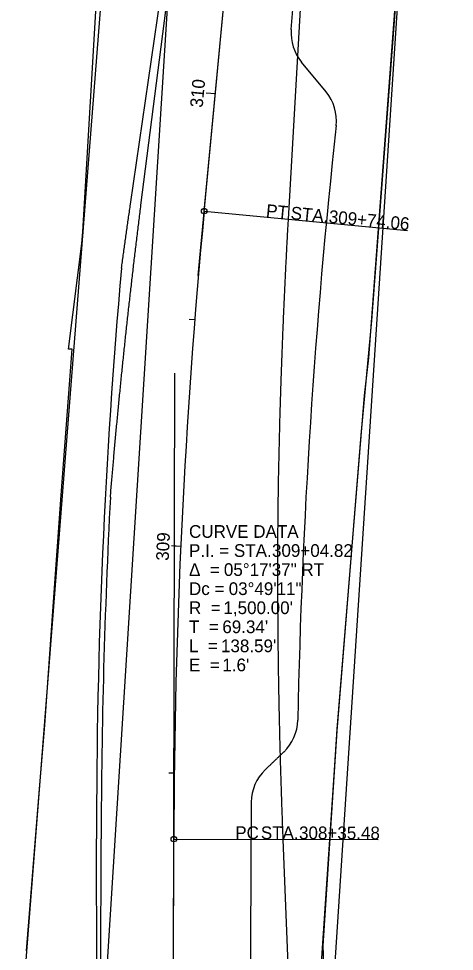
# Model space of a CAD drawing. Extents: x 219353 to 221640, y 361458 to 364236.
# Drawn here: x 220538 to 220633.9, y 362269.2 to 362474.7 of the extents above; entities that cross this region are included whole.
import ezdxf

# ---------------------------------------------------------------- set-up
doc = ezdxf.new("R2010")
doc.units = 0
for name, color, linetype in [('Default', 7, 'Continuous'), ('DR_X_Cells', 7, 'Continuous'), ('DR_X_GenericNode', 7, 'Continuous'), ('DR_X_Storm_Sewer', 7, 'Continuous'), ('DT_X_Contour_Major', 7, 'Continuous'), ('DT_X_Contour_Minor', 7, 'Continuous'), ('SC_ProfileRun2', 7, 'Continuous'), ('SC_ProfileRun3', 7, 'Continuous'), ('UT_X_Sanitary_Cells', 7, 'Continuous')]:
    doc.layers.add(name, color=color, linetype=linetype)

msp = doc.modelspace()

# ---------------------------------------------------------------- linework, layer by layer
at = {"layer": 'Default'}
for p, q in [((220606.11, 362243.12), (220684.52, 363442.47)), ((220589.94, 362047.45), (220608.12, 362317.78))]:
    msp.add_line(p, q, dxfattribs=at)
msp.add_open_spline([(220592.27, 362309.18), (220592.28, 362309.19), (220592.45, 362309.35), (220592.79, 362309.68), (220593.29, 362310.16), (220593.8, 362310.65), (220594.31, 362311.13), (220594.81, 362311.62), (220595.32, 362312.11), (220595.83, 362312.59), (220596.18, 362312.92), (220596.35, 362313.1), (220596.37, 362313.11)], degree=3, dxfattribs=at)
at = {"layer": 'DR_X_Cells'}
for p, q in [((220578.85, 362432.29), (220623.65, 362428.04)), ((220572.17, 362293.91), (220617.17, 362293.82))]:
    msp.add_line(p, q, dxfattribs=at)
for centre in [(220578.85, 362432.29), (220572.17, 362293.91)]:
    msp.add_circle(centre, 0.6, dxfattribs=at)
at = {"layer": 'DR_X_GenericNode'}
for p, q in [((220631.67, 363446.41), (220538.01, 362247.29)), ((220541.47, 362010.88), (220631.67, 363446.41)), ((220562.63, 362433.83), (220580.78, 362558.61)), ((220598.01, 362472.29), (220604.67, 362556.35)), ((220615.74, 362408.19), (220621, 362477.12)), ((220605.68, 362458.59), (220600.27, 362465.13)), ((220613.44, 362382.96), (220615.74, 362408.19)), ((220608.12, 362317.78), (220613.44, 362382.96)), ((220605.04, 362270.37), (220608.12, 362317.78)), ((220555.31, 362213.3), (220555.17, 362293.95)), ((220589.06, 362242.18), (220589.17, 362293.88)), ((220606.11, 362243.12), (220605.04, 362270.37))]:
    msp.add_line(p, q, dxfattribs=at)
for centre, radius, start, end in [((220607.98, 362471.5), 10, 175.4681, 219.5875), ((220597.98, 362452.21), 10, 353.7514, 39.5875), ((222072.17, 362290.8), 1473, 173.75144, 178.85872), ((221945.54, 362296.32), 1390.38, 174.90785, 180.0978), ((220589.46, 362320.34), 10, 313.6715, 358.8587), ((220599.21, 362301.98), 10, 133.9039, 179.5652), ((222072.17, 362290.8), 1483, 179.5652, 179.88107)]:
    msp.add_arc(centre, radius, start, end, dxfattribs=at)
msp.add_open_spline([(220560.65, 362419.73), (220560.69, 362419.96), (220560.75, 362420.43), (220560.85, 362421.14), (220560.94, 362421.85), (220561.04, 362422.55), (220561.14, 362423.26), (220561.23, 362423.96), (220561.33, 362424.67), (220561.43, 362425.37), (220561.53, 362426.08), (220561.63, 362426.78), (220561.72, 362427.48), (220561.82, 362428.19), (220561.92, 362428.89), (220562.02, 362429.6), (220562.12, 362430.3), (220562.22, 362431.01), (220562.32, 362431.71), (220562.43, 362432.42), (220562.53, 362433.12), (220562.6, 362433.59), (220562.63, 362433.83)], degree=3, dxfattribs=at)
at = {"layer": 'DT_X_Contour_Major'}
for p, q in [((220577.51, 362418.1), (220596.38, 362617.24)), ((220578.85, 362432.29), (220596.38, 362617.24)), ((220571.7, 362066.21), (220572.38, 362396.56)), ((220571.7, 362066.21), (220572.17, 362293.91)), ((220571.8, 362118.35), (220572.17, 362293.91)), ((220571.8, 362118.35), (220572.17, 362293.91))]:
    msp.add_line(p, q, dxfattribs=at)
msp.add_arc((222072.17, 362290.8), 1500, 174.58751, 179.88107, dxfattribs=at)
msp.add_arc((222072.17, 362290.8), 1500, 174.58751, 179.88107, dxfattribs=at)
at = {"layer": 'DT_X_Contour_Minor'}
for p, q in [((220564.94, 362433.61), (220580.78, 362558.61)), ((220564.94, 362433.61), (220580.78, 362558.61)), ((220564.94, 362433.61), (220580.78, 362558.61)), ((220564.94, 362433.61), (220580.78, 362558.61)), ((220564.94, 362433.61), (220580.78, 362558.61)), ((220597.41, 362430.53), (220604.67, 362556.35)), ((220597.41, 362430.53), (220604.67, 362556.35)), ((220597.41, 362430.53), (220604.67, 362556.35)), ((220615.12, 362399.96), (220622.66, 362501.46)), ((220615.12, 362399.96), (220622.66, 362501.46)), ((220614.15, 362391.69), (220615.12, 362399.96)), ((220614.15, 362391.69), (220615.12, 362399.96)), ((220555.92, 362173.47), (220556.17, 362293.95)), ((220555.92, 362173.47), (220556.17, 362293.95)), ((220556.01, 362215.03), (220556.17, 362293.95)), ((220556.01, 362215.03), (220556.17, 362293.95)), ((220556.01, 362215.03), (220556.17, 362293.95)), ((220599.02, 362223.38), (220596.25, 362293.86)), ((220598.09, 362247.17), (220596.25, 362293.86)), ((220598.09, 362247.17), (220596.25, 362293.86))]:
    msp.add_line(p, q, dxfattribs=at)
for points in [[(220548.97, 362401.87), (220551.9, 362425.19), (220552.11, 362427.73), (220555.49, 362485.14), (220558.19, 362519.47), (220559.13, 362527.53), (220560.7, 362544.5), (220563.39, 362577.56), (220564.51, 362592.82), (220566.29, 362622.53), (220566.62, 362624.87), (220555.18, 362626.91)], [(220539.71, 362269.28), (220542.65, 362305.9), (220543.74, 362319.05), (220545.68, 362346.19), (220547.38, 362369.7), (220549.8, 362401.88), (220548.97, 362401.87)], [(220604.98, 362269.51), (220608.14, 362318.12), (220614.15, 362391.69)], [(220604.98, 362269.51), (220608.14, 362318.12), (220614.15, 362391.69)]]:
    msp.add_lwpolyline(points, dxfattribs=at)
msp.add_arc((222072.17, 362290.8), 1516, 177.03444, 179.88107, dxfattribs=at)
msp.add_arc((222072.17, 362290.8), 1516, 177.03444, 179.88107, dxfattribs=at)
msp.add_arc((222072.17, 362290.8), 1516, 177.03444, 179.88107, dxfattribs=at)
msp.add_arc((222072.17, 362290.8), 1516, 177.03444, 179.88107, dxfattribs=at)
msp.add_arc((222072.17, 362290.8), 1516, 177.03444, 179.88107, dxfattribs=at)
for points in [[(220558.2, 362369.23), (220558.29, 362370.31), (220558.47, 362372.46), (220558.75, 362375.68), (220559.03, 362378.91), (220559.32, 362382.14), (220559.62, 362385.36), (220559.93, 362388.58), (220560.24, 362391.8), (220560.56, 362395.03), (220560.89, 362398.25), (220561.22, 362401.47), (220561.56, 362404.68), (220561.91, 362407.9), (220562.27, 362411.12), (220562.63, 362414.33), (220563, 362417.55), (220563.37, 362420.76), (220563.75, 362423.97), (220564.14, 362427.19), (220564.54, 362430.4), (220564.8, 362432.54), (220564.94, 362433.61)], [(220558.2, 362369.23), (220558.29, 362370.31), (220558.47, 362372.46), (220558.75, 362375.68), (220559.03, 362378.91), (220559.32, 362382.14), (220559.62, 362385.36), (220559.93, 362388.58), (220560.24, 362391.8), (220560.56, 362395.03), (220560.89, 362398.25), (220561.22, 362401.47), (220561.56, 362404.68), (220561.91, 362407.9), (220562.27, 362411.12), (220562.63, 362414.33), (220563, 362417.55), (220563.37, 362420.76), (220563.75, 362423.97), (220564.14, 362427.19), (220564.54, 362430.4), (220564.8, 362432.54), (220564.94, 362433.61)], [(220558.2, 362369.23), (220558.29, 362370.31), (220558.47, 362372.46), (220558.75, 362375.68), (220559.03, 362378.91), (220559.32, 362382.14), (220559.62, 362385.36), (220559.93, 362388.58), (220560.24, 362391.8), (220560.56, 362395.03), (220560.89, 362398.25), (220561.22, 362401.47), (220561.56, 362404.68), (220561.91, 362407.9), (220562.27, 362411.12), (220562.63, 362414.33), (220563, 362417.55), (220563.37, 362420.76), (220563.75, 362423.97), (220564.14, 362427.19), (220564.54, 362430.4), (220564.8, 362432.54), (220564.94, 362433.61)], [(220558.2, 362369.23), (220558.29, 362370.31), (220558.47, 362372.46), (220558.75, 362375.68), (220559.03, 362378.91), (220559.32, 362382.14), (220559.62, 362385.36), (220559.93, 362388.58), (220560.24, 362391.8), (220560.56, 362395.03), (220560.89, 362398.25), (220561.22, 362401.47), (220561.56, 362404.68), (220561.91, 362407.9), (220562.27, 362411.12), (220562.63, 362414.33), (220563, 362417.55), (220563.37, 362420.76), (220563.75, 362423.97), (220564.14, 362427.19), (220564.54, 362430.4), (220564.8, 362432.54), (220564.94, 362433.61)], [(220558.2, 362369.23), (220558.29, 362370.31), (220558.47, 362372.46), (220558.75, 362375.68), (220559.03, 362378.91), (220559.32, 362382.14), (220559.62, 362385.36), (220559.93, 362388.58), (220560.24, 362391.8), (220560.56, 362395.03), (220560.89, 362398.25), (220561.22, 362401.47), (220561.56, 362404.68), (220561.91, 362407.9), (220562.27, 362411.12), (220562.63, 362414.33), (220563, 362417.55), (220563.37, 362420.76), (220563.75, 362423.97), (220564.14, 362427.19), (220564.54, 362430.4), (220564.8, 362432.54), (220564.94, 362433.61)], [(220595.15, 362367.32), (220595.16, 362368.37), (220595.19, 362370.48), (220595.25, 362373.64), (220595.31, 362376.8), (220595.38, 362379.96), (220595.46, 362383.12), (220595.54, 362386.28), (220595.63, 362389.44), (220595.73, 362392.6), (220595.83, 362395.76), (220595.94, 362398.92), (220596.06, 362402.08), (220596.18, 362405.24), (220596.31, 362408.41), (220596.45, 362411.57), (220596.59, 362414.73), (220596.74, 362417.89), (220596.9, 362421.05), (220597.06, 362424.21), (220597.23, 362427.37), (220597.35, 362429.48), (220597.41, 362430.53)], [(220595.15, 362367.32), (220595.16, 362368.37), (220595.19, 362370.48), (220595.25, 362373.64), (220595.31, 362376.8), (220595.38, 362379.96), (220595.46, 362383.12), (220595.54, 362386.28), (220595.63, 362389.44), (220595.73, 362392.6), (220595.83, 362395.76), (220595.94, 362398.92), (220596.06, 362402.08), (220596.18, 362405.24), (220596.31, 362408.41), (220596.45, 362411.57), (220596.59, 362414.73), (220596.74, 362417.89), (220596.9, 362421.05), (220597.06, 362424.21), (220597.23, 362427.37), (220597.35, 362429.48), (220597.41, 362430.53)], [(220595.15, 362367.32), (220595.16, 362368.37), (220595.19, 362370.48), (220595.25, 362373.64), (220595.31, 362376.8), (220595.38, 362379.96), (220595.46, 362383.12), (220595.54, 362386.28), (220595.63, 362389.44), (220595.73, 362392.6), (220595.83, 362395.76), (220595.94, 362398.92), (220596.06, 362402.08), (220596.18, 362405.24), (220596.31, 362408.41), (220596.45, 362411.57), (220596.59, 362414.73), (220596.74, 362417.89), (220596.9, 362421.05), (220597.06, 362424.21), (220597.23, 362427.37), (220597.35, 362429.48), (220597.41, 362430.53)], [(220596.25, 362293.86), (220596.2, 362295.09), (220596.11, 362297.53), (220595.98, 362301.2), (220595.85, 362304.87), (220595.74, 362308.54), (220595.63, 362312.21), (220595.54, 362315.88), (220595.45, 362319.55), (220595.37, 362323.22), (220595.3, 362326.89), (220595.24, 362330.56), (220595.19, 362334.24), (220595.15, 362337.91), (220595.12, 362341.59), (220595.09, 362345.26), (220595.08, 362348.94), (220595.07, 362352.61), (220595.08, 362356.29), (220595.09, 362359.96), (220595.11, 362363.64), (220595.14, 362366.09), (220595.15, 362367.32)], [(220596.25, 362293.86), (220596.2, 362295.09), (220596.11, 362297.53), (220595.98, 362301.2), (220595.85, 362304.87), (220595.74, 362308.54), (220595.63, 362312.21), (220595.54, 362315.88), (220595.45, 362319.55), (220595.37, 362323.22), (220595.3, 362326.89), (220595.24, 362330.56), (220595.19, 362334.24), (220595.15, 362337.91), (220595.12, 362341.59), (220595.09, 362345.26), (220595.08, 362348.94), (220595.07, 362352.61), (220595.08, 362356.29), (220595.09, 362359.96), (220595.11, 362363.64), (220595.14, 362366.09), (220595.15, 362367.32)], [(220596.25, 362293.86), (220596.2, 362295.09), (220596.11, 362297.53), (220595.98, 362301.2), (220595.85, 362304.87), (220595.74, 362308.54), (220595.63, 362312.21), (220595.54, 362315.88), (220595.45, 362319.55), (220595.37, 362323.22), (220595.3, 362326.89), (220595.24, 362330.56), (220595.19, 362334.24), (220595.15, 362337.91), (220595.12, 362341.59), (220595.09, 362345.26), (220595.08, 362348.94), (220595.07, 362352.61), (220595.08, 362356.29), (220595.09, 362359.96), (220595.11, 362363.64), (220595.14, 362366.09), (220595.15, 362367.32)]]:
    msp.add_open_spline(points, degree=3, dxfattribs=at)
at = {"layer": 'SC_ProfileRun2'}
for p, q in [((220578.85, 362432.29), (220623.65, 362428.04)), ((220572.17, 362293.91), (220617.17, 362293.82))]:
    msp.add_line(p, q, dxfattribs=at)
for centre in [(220578.85, 362432.29), (220572.17, 362293.91)]:
    msp.add_circle(centre, 0.6, dxfattribs=at)
at = {"layer": 'SC_ProfileRun3'}
for p, q in [((220581.3, 362458.11), (220579.31, 362458.3)), ((220573.69, 362358.42), (220572.49, 362358.47))]:
    msp.add_line(p, q, dxfattribs=at)
at = {"layer": 'UT_X_Sanitary_Cells'}
for p, q in [((220581.3, 362458.11), (220579.31, 362458.3)), ((220576.78, 362408.32), (220575.58, 362408.41)), ((220573.69, 362358.42), (220571.69, 362358.51)), ((220572.27, 362308.44), (220571.07, 362308.45))]:
    msp.add_line(p, q, dxfattribs=at)

# ---------------------------------------------------------------- texts
at = {"layer": 'DR_X_Cells'}
for s, rotation, p in [('PT', 354.5875, (220592.38, 362431.05)), (' STA. ', 354.5875, (220596.77, 362430.63)), ('309+74.06', 354.5875, (220606.18, 362429.74)), ('PC', 359.8811, (220585.69, 362293.93)), (' STA. ', 359.8811, (220590.28, 362293.92)), ('308+35.48', 359.8811, (220599.73, 362293.9))]:
    msp.add_text(s, height=2.8, rotation=rotation, dxfattribs=at).set_placement(p)
at = {"layer": 'DR_X_Storm_Sewer'}
for s, p in [('CURVE DATA', (220575.51, 362360.3)), ('P.I. = STA. ', (220575.51, 362356.1)), ('309+04.82', (220593.78, 362356.1)), ('Δ  = ', (220575.51, 362351.9)), ('05°17\'37" RT', (220583.19, 362351.9)), ('Dc = ', (220575.51, 362347.7)), ('03°49\'11"', (220584.25, 362347.7)), ('R  = ', (220575.51, 362343.5)), ("1,500.00'", (220583.09, 362343.5)), ('T  = ', (220575.51, 362339.3)), ("69.34'", (220582.85, 362339.3)), ('L  = ', (220575.51, 362335.1)), ("138.59'", (220582.55, 362335.1)), ('E  = ', (220575.51, 362330.9)), ("1.6'", (220582.85, 362330.9))]:
    msp.add_text(s, height=2.8, dxfattribs=at).set_placement(p)
at = {"layer": 'SC_ProfileRun2'}
for s, rotation, p in [('PT', 354.5875, (220592.38, 362431.05)), (' STA. ', 354.5875, (220596.77, 362430.63)), ('309+74.06', 354.5875, (220606.18, 362429.74)), ('PC', 359.8811, (220585.69, 362293.93)), (' STA. ', 359.8811, (220590.28, 362293.92)), ('308+35.48', 359.8811, (220599.73, 362293.9))]:
    msp.add_text(s, height=2.8, rotation=rotation, dxfattribs=at).set_placement(p)
at = {"layer": 'SC_ProfileRun3'}
msp.add_text('310', height=2.8, rotation=84.5875, dxfattribs=at).set_placement((220578.5, 362455.02))
at = {"layer": 'UT_X_Sanitary_Cells'}
for s, rotation, p in [('310', 84.5875, (220578.5, 362455.02)), ('309', 87.4164, (220571.04, 362355.21))]:
    msp.add_text(s, height=2.8, rotation=rotation, dxfattribs=at).set_placement(p)

doc.saveas('drawing.dxf')
